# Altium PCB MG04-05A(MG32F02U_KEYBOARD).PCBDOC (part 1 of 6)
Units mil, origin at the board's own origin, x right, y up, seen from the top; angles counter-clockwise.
Board outline 17912.8 x 10422.68 mil, 2 copper layers (Top Layer, Bottom Layer); 623 components, 347 nets, 1816 pads, 821 vias.
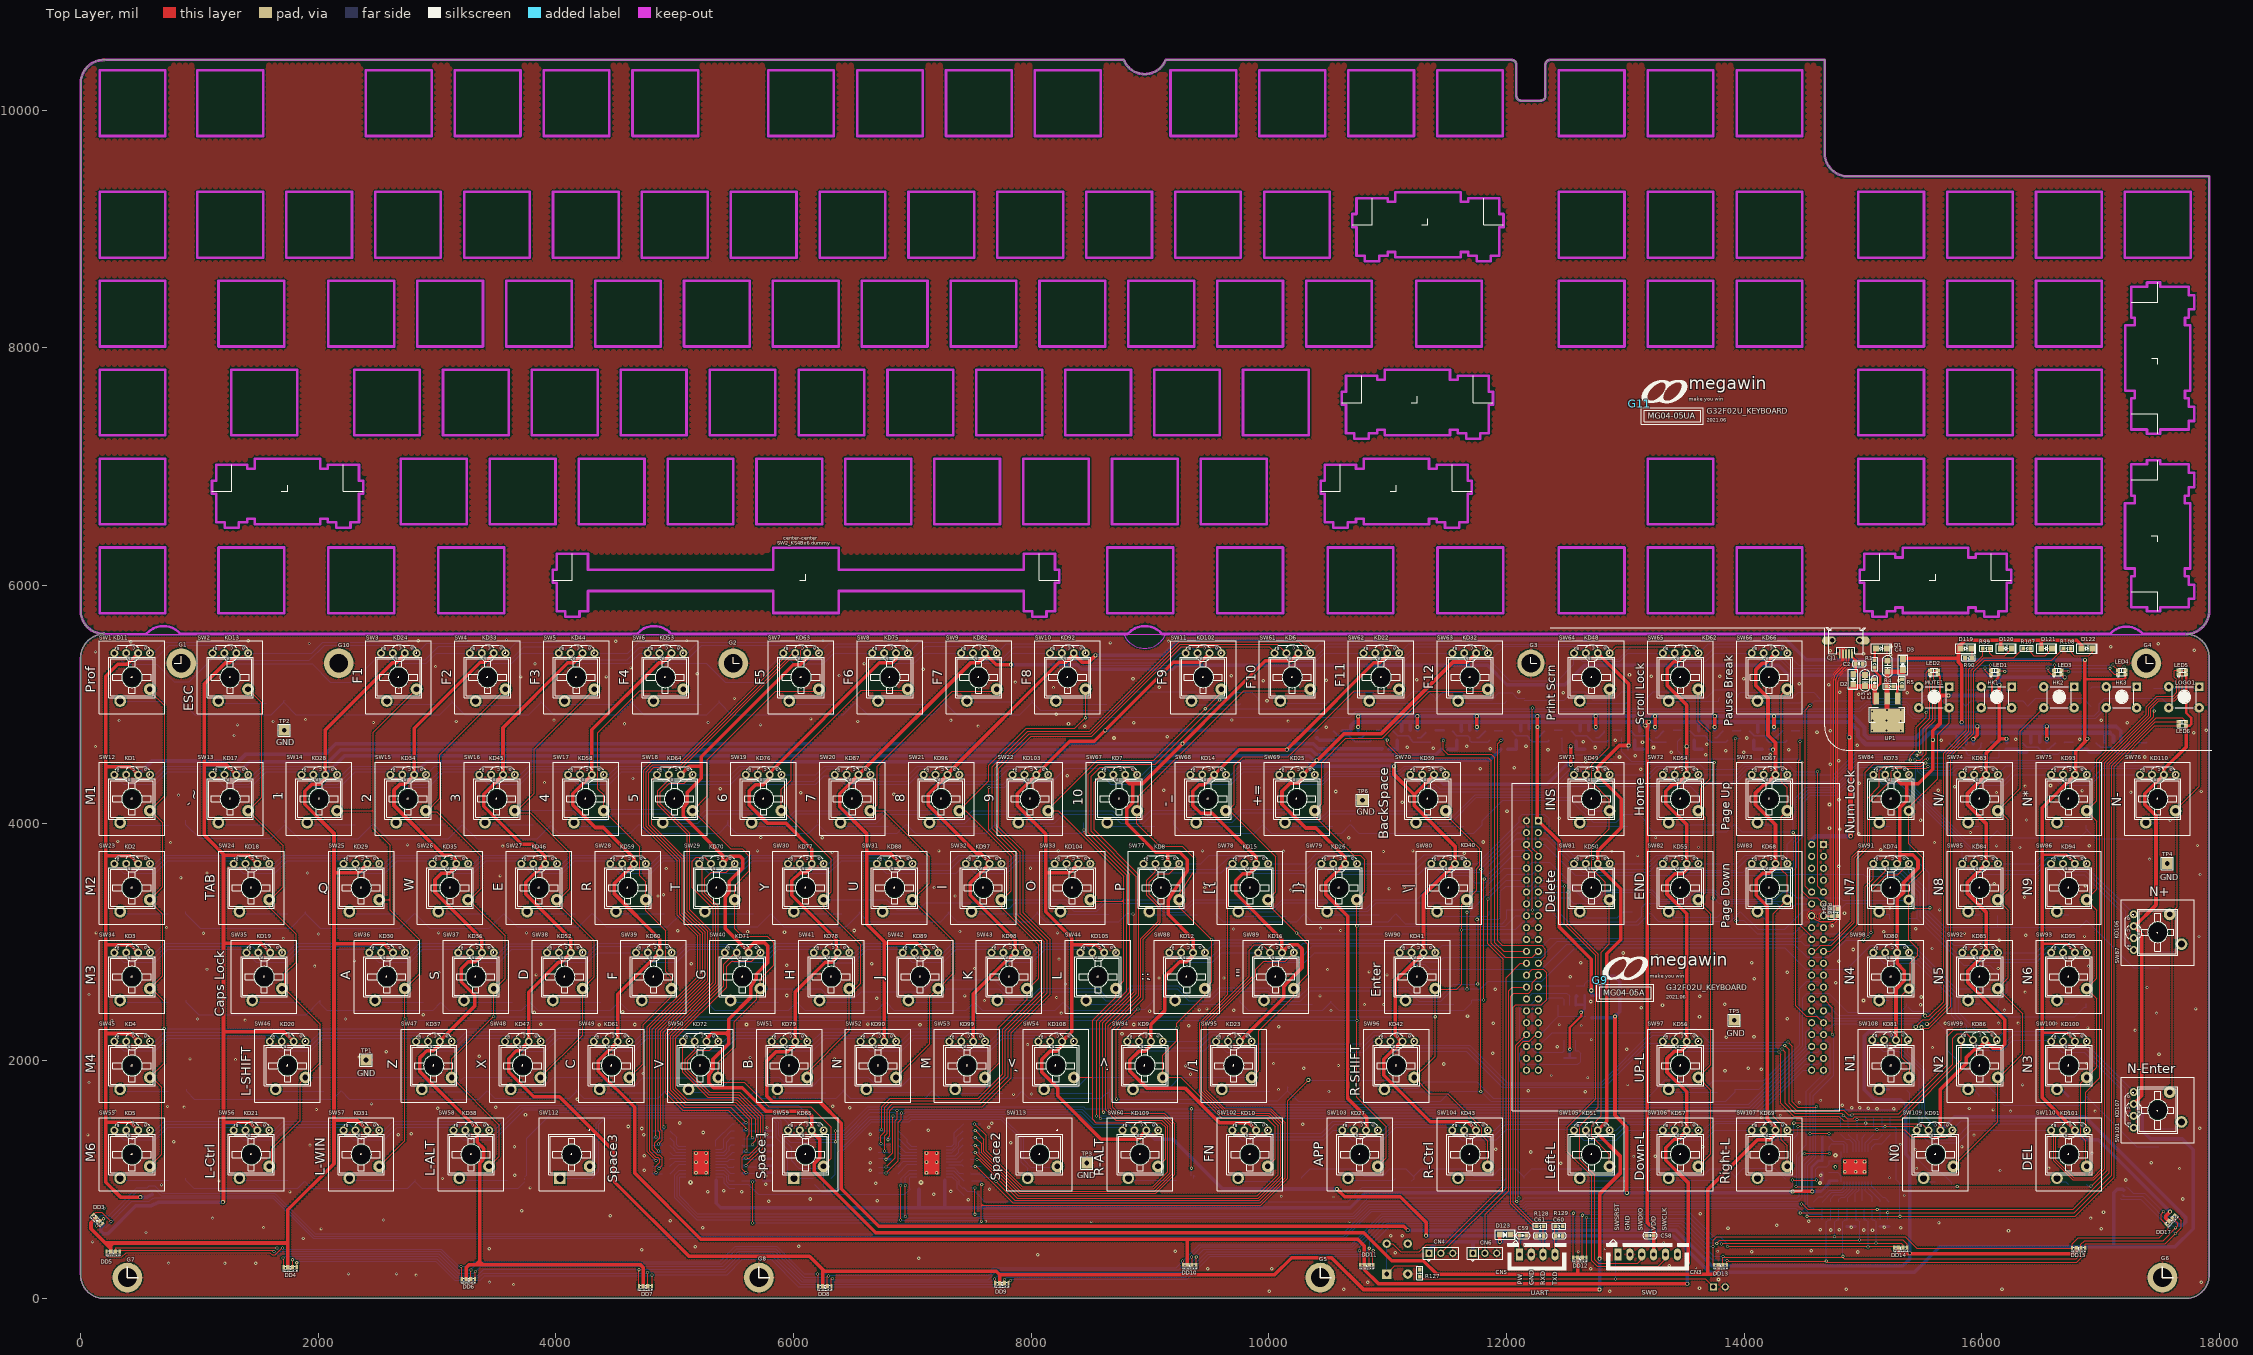
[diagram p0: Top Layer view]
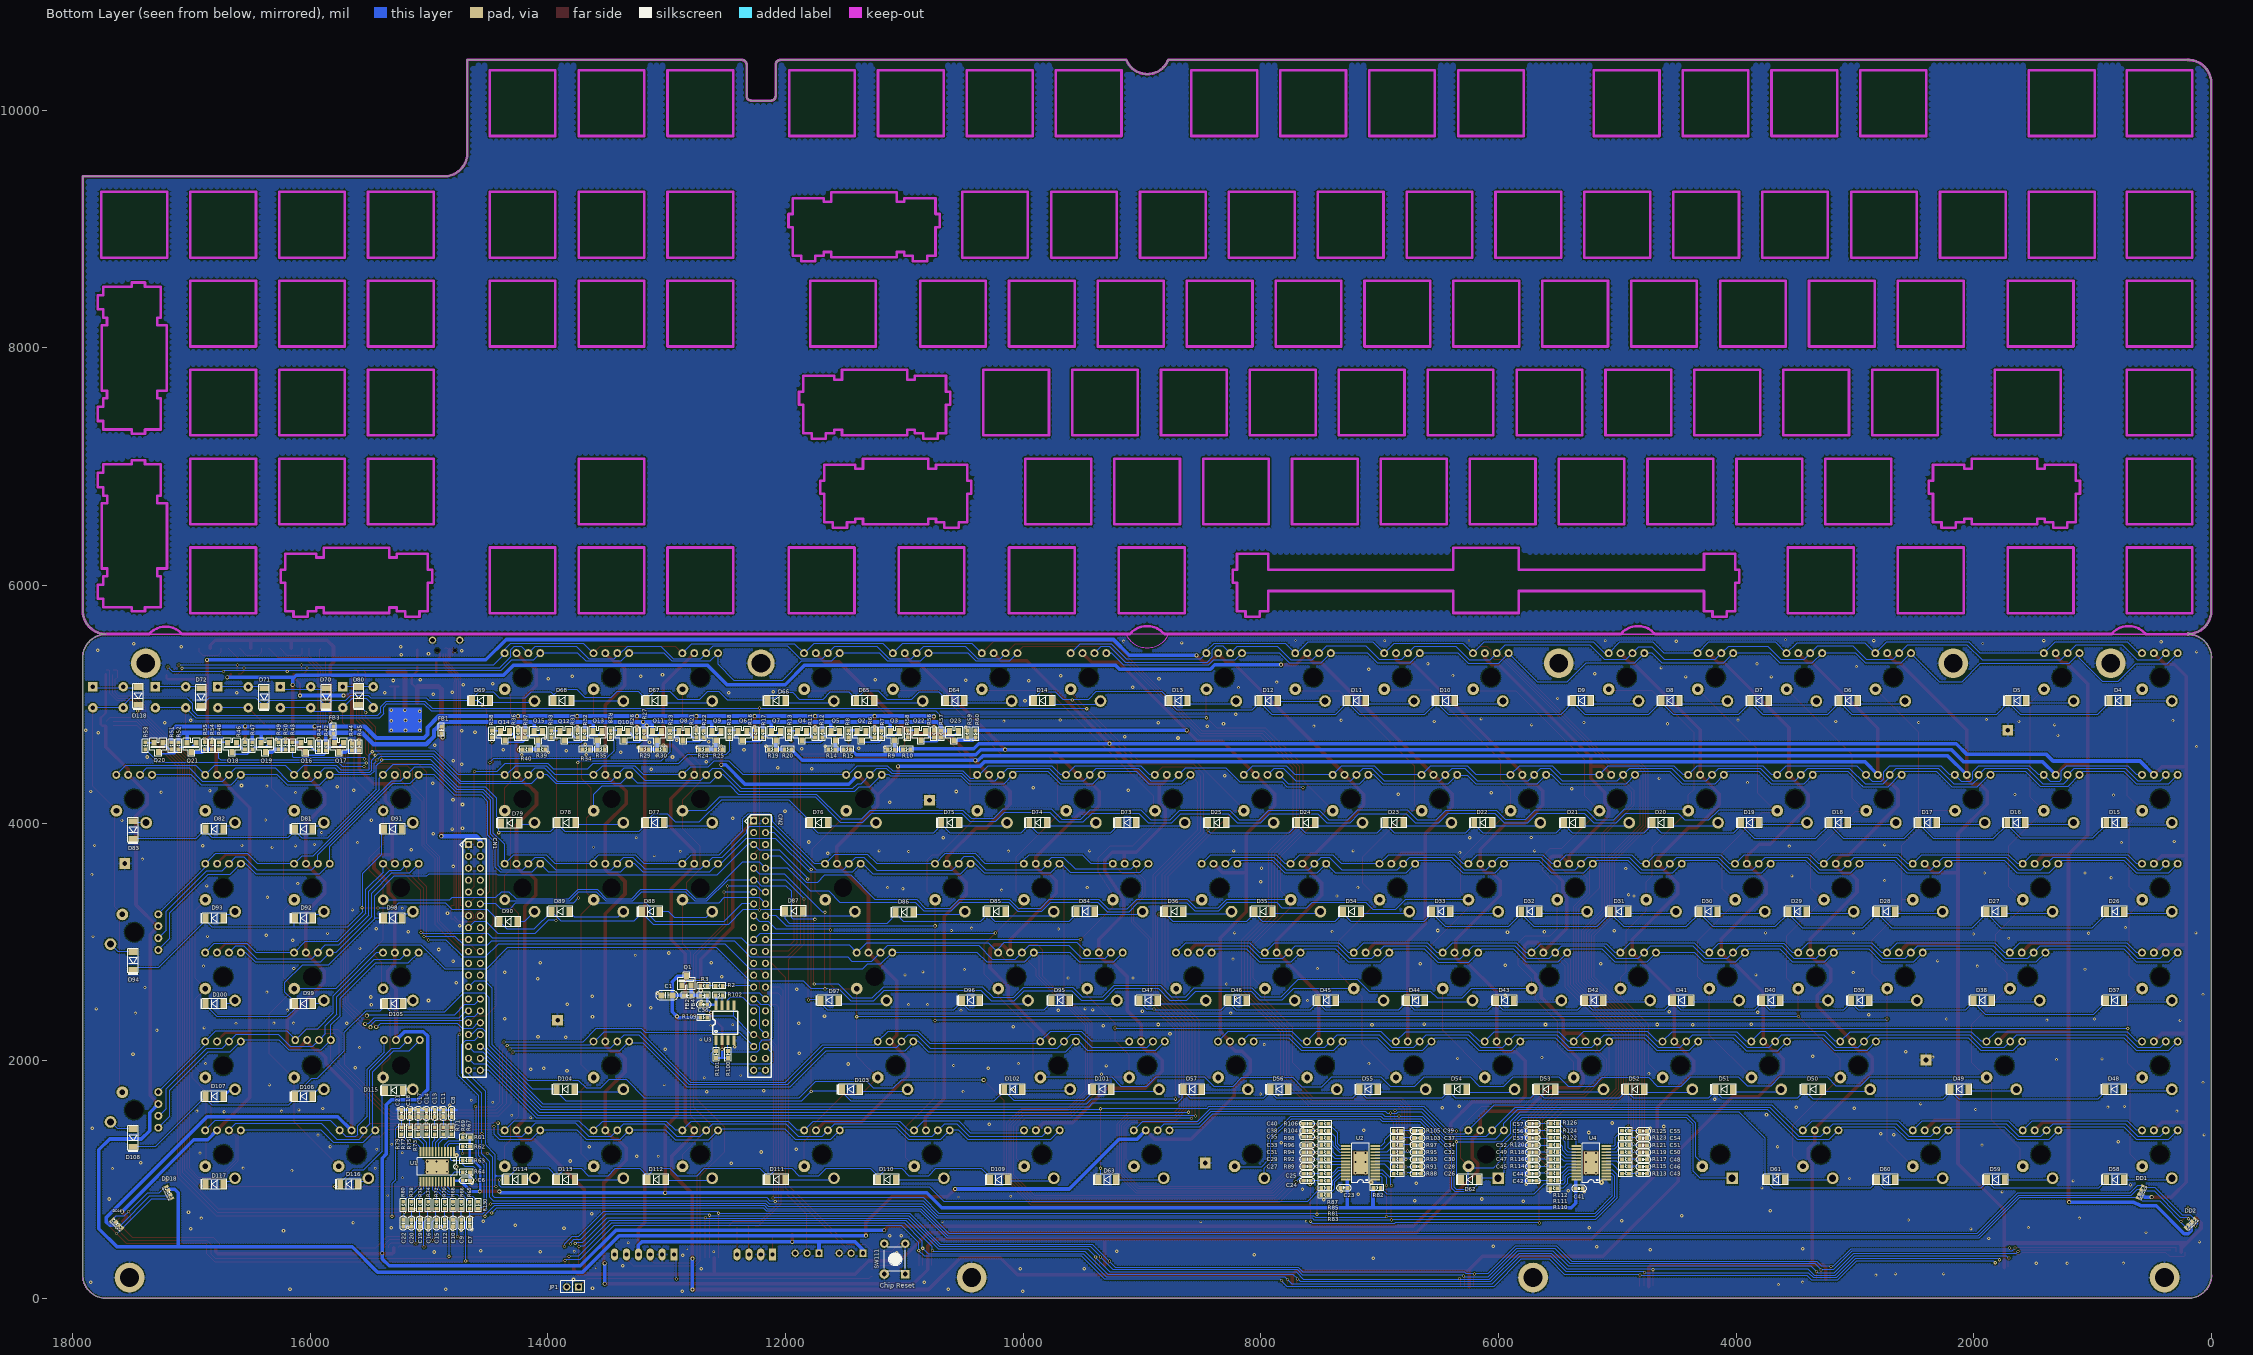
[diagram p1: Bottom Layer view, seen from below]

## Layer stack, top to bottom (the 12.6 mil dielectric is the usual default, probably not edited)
Top Layer: signal copper 1.4
Dielectric: dielectric 12.6, FR-4, Dk 4.8
Bottom Layer: signal copper 1.4

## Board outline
0,198.37 0,5393.85 cw(c196.85,5393.85) 196.85,5590.7 196.85,5590.95 cw(c196.85,5787.8) 0,5787.8 0,10225.83 cw(c196.85,10225.83) 196.85,10422.68 8778.93,10422.68 ccw(c8954.69,10492.11) 9130.28,10422.25 12042.69,10422.25 cw(c12042.7,10382.9) 12082.06,10382.89 12082.06,10119.37 ccw(c12121.43,10119.37) 12121.43,10080 12286.78,10080 ccw(c12286.78,10119.37) 12326.15,10119.37 12326.15,10382.89 cw(c12365.52,10382.88) 12365.52,10422.25 14676.35,10422.25 14676.35,9639.56 ccw(c14873.2,9639.56) 14873.2,9442.71 17912.8,9442.71 17912.8,5787.19 cw(c17715.95,5787.19) 17715.95,5590.34 17715.95,5590.55 cw(c17715.95,5393.7) 17912.8,5393.7 17912.8,198.37 cw(c17715.09,197.71) 17715.75,0 197.04,0 cw(c197.71,197.71)

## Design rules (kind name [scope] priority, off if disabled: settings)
Clearance 10 [All] p1 off: gap=10
Clearance 7_USB [All] p2 off: gap=7
Clearance 6_CLK [All] p3 off: gap=6
Clearance 5 [All] p4: gap=5
HoleSize [All] p1: absolutevalues=TRUE maxlimit=500 minlimit=1 maxpercent=80.000 minpercent=20.000
MinimumSolderMaskSliver [All] p1 off: minsoldermaskwidth=10
PolygonConnect via [isvia] p1: connectstyle=Direct reliefconductorwidth=10 reliefentries=4 polygonreliefangle="90 Angle"
PolygonConnect 15 [All] p2: connectstyle=Relief reliefconductorwidth=15 reliefentries=4 polygonreliefangle="90 Angle"
RoutingVias [All] p1: holewidth=16 width=25 viastyle="Through Hole" minholewidth=16 minwidth=25 maxholewidth=28 maxwidth=50
SilkToSilkClearance [All] p1 off: silktosilkclearance=10
SilkscreenOverComponentPads [All] p1 off: minsilkscreentomaskgap=10
SolderMaskExpansion [All] p1: expansion=4
Width [All] p1: maxlimit=100 minlimit=6 preferedwidth=10
24 further rules are at their usual default settings.

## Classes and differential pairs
net class LED_Y[0..10]: LED_Y0 LED_Y1 LED_Y2 LED_Y3 LED_Y4 LED_Y5 LED_Y6 LED_Y7 LED_Y8 LED_Y9 LED_Y10
net class LED_R[0..14]: LED_R0 LED_R1 LED_R2 LED_R3 LED_R4 LED_R5 LED_R6 LED_R7 LED_R8 LED_R9 LED_R10 LED_R11 LED_R12 LED_R13 LED_R14
net class LED_G[0..14]: LED_G0 LED_G1 LED_G2 LED_G3 LED_G4 LED_G5 LED_G6 LED_G7 LED_G8 LED_G9 LED_G10 LED_G11 LED_G12 LED_G13 LED_G14
net class LED_B[0..14]: LED_B0 LED_B1 LED_B2 LED_B3 LED_B4 LED_B5 LED_B6 LED_B7 LED_B8 LED_B9 LED_B10 LED_B11 LED_B12 LED_B13 LED_B14
net class KB_R[0..10]: KB_R0 KB_R1 KB_R2 KB_R3 KB_R4 KB_R5 KB_R6 KB_R7 KB_R8 KB_R9 KB_R10
net class KB_C[0..11]: KB_C0 KB_C1 KB_C2 KB_C3 KB_C4 KB_C5 KB_C6 KB_C7 KB_C8 KB_C9 KB_C10 KB_C11
component class "04_MCU IF": C6 C7 C8 C9 C10 C11 C12 C13 C14 C15 C16 C17 C18 C19 C20 C21 C22 C23 C24 C25 C26 C27 C28 C29 C30 C31 C32 C33 C34 C35 C36 C37 C38 C39 C40 C41 C42 C43 C44 C45 C46 C47 C48 C49 C50 C51 C52 C53 C54 C55 C56 C57 C58 C59 C60 C61 CN1 CN2 CN3 CN4 CN5 CN6 D119 D120 D121 D122 D123 FB4 JP1 R61 R62 R63 R64 R65 R66 R67 R68 R69 R70 R71 R72 R73 R74 R75 R76 R77 R78 R79 R80 R81 R82 R83 R84 R85 R86 R87 R88 R89 R90 R91 R92 R93 R94 R95 R96 R97 R98 R99 R100 R101 R102 R103 R104 R105 R106 R107 R108 R109 R110 R111 R112 R113 R114 R115 R116 R117 R118 R119 R120 R121 R122 R123 R124 R125 R126 R127 R128 R129 R130 SW111 U1 U2 U3 U4
component class "03_LED Matrix": DD1 DD2 DD3 DD4 DD5 DD6 DD7 DD8 DD9 DD10 DD11 DD12 DD13 DD14 DD15 DD16 DD17 DD18 KD1 KD2 KD3 KD4 KD5 KD6 KD7 KD8 KD9 KD10 KD11 KD12 KD13 KD14 KD15 KD16 KD17 KD18 KD19 KD20 KD21 KD22 KD23 KD24 KD25 KD26 KD27 KD28 KD29 KD30 KD31 KD32 KD33 KD34 KD35 KD36 KD37 KD38 KD39 KD40 KD41 KD42 KD43 KD44 KD45 KD46 KD47 KD48 KD49 KD50 KD51 KD52 KD53 KD54 KD55 KD56 KD57 KD58 KD59 KD60 KD61 KD62 KD63 KD64 KD65 KD66 KD67 KD68 KD69 KD70 KD71 KD72 KD73 KD74 KD75 KD76 KD77 KD78 KD79 KD80 KD81 KD82 KD83 KD84 KD85 KD86 KD87 KD88 KD89 KD90 KD91 KD92 KD93 KD94 KD95 KD96 KD97 KD98 KD99 KD100 KD101 KD102 KD103 KD104 KD105 KD106 KD107 KD108 KD109 KD110 LED1 LED2 LED3 LED4 LED5 LED6 Q2 Q3 Q4 Q5 Q6 Q7 Q8 Q9 Q10 Q11 Q12 Q13 Q14 Q15 Q16 Q17 Q18 Q19 Q20 Q21 Q22 Q23 R6 R7 R8 R9 R10 R11 R12 R13 R14 R15 R16 R17 R18 R19 R20 R21 R22 R23 R24 R25 R26 R27 R28 R29 R30 R31 R32 R33 R34 R35 R36 R37 R38 R39 R40 R41 R42 R43 R44 R45 R46 R47 R48 R49 R50 R51 R52 R53 R54 R55 R56 R57 R58 R59 R60
component class "02_Key Matrix": D4 D5 D6 D7 D8 D9 D10 D11 D12 D13 D14 D15 D16 D17 D18 D19 D20 D21 D22 D23 D24 D25 D26 D27 D28 D29 D30 D31 D32 D33 D34 D35 D36 D37 D38 D39 D40 D41 D42 D43 D44 D45 D46 D47 D48 D49 D50 D51 D52 D53 D54 D55 D56 D57 D58 D59 D60 D61 D62 D63 D64 D65 D66 D67 D68 D69 D70 D71 D72 D73 D74 D75 D76 D77 D78 D79 D80 D81 D82 D83 D84 D85 D86 D87 D88 D89 D90 D91 D92 D93 D94 D95 D96 D97 D98 D99 D100 D101 D102 D103 D104 D105 D106 D107 D108 D109 D110 D111 D112 D113 D114 D115 D116 D117 D118 HK1 HK2 HK3 Logo1 Mute1 SW1 SW2 SW3 SW4 SW5 SW6 SW7 SW8 SW9 SW10 SW11 SW12 SW13 SW14 SW15 SW16 SW17 SW18 SW19 SW20 SW21 SW22 SW23 SW24 SW25 SW26 SW27 SW28 SW29 SW30 SW31 SW32 SW33 SW34 SW35 SW36 SW37 SW38 SW39 SW40 SW41 SW42 SW43 SW44 SW45 SW46 SW47 SW48 SW49 SW50 SW51 SW52 SW53 SW54 SW55 SW56 SW57 SW58 SW59 SW60 SW61 SW62 SW63 SW64 SW65 SW66 SW67 SW68 SW69 SW70 SW71 SW72 SW73 SW74 SW75 SW76 SW77 SW78 SW79 SW80 SW81 SW82 SW83 SW84 SW85 SW86 SW87 SW88 SW89 SW90 SW91 SW92 SW93 SW94 SW95 SW96 SW97 SW98 SW99 SW100 SW101 SW102 SW103 SW104 SW105 SW106 SW107 SW108 SW109 SW110 SW112 SW113
component class "01_Power Supply": C1 C2 C3 C4 C5 CJ1 D1 D2 D3 FB1 FB2 FB3 G1 G2 G3 G4 G5 G6 G7 G8 G9 G10 G11 Q1 R1 R2 R3 R4 R5 TP1 TP2 TP3 TP4 TP5 TP6 UP1

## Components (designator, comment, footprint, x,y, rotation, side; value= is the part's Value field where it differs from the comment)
C1 "33uF/10V" C-0805 12997,2550 r0 bottom
C2 "1uF" C-0603 14967,5340 r0 top
C3 "10uF/10V" C-0805 15017,5200 r90 top
C4 "0.1uF" C-0603 15097,5180 r90 top
C5 "10uF/10V" C-0805 15207,5320 r90 top
C6 "0.1uF" C-0603 14684.64,992.74 r180 bottom
C7 "22pF" C-0603 14656,633.89 r270 bottom
C8 "22pF" C-0603 14808.15,1556.47 r90 bottom
C9 "22pF" C-0603 14726,633.89 r270 bottom
C10 "22pF" C-0603 14796,633.89 r270 bottom
C11 "22pF" C-0603 14880,1556.47 r90 bottom
C12 "22pF" C-0603 14866,633.89 r270 bottom
C13 "22pF" C-0603 14950,1556.47 r90 bottom
C14 "22pF" C-0603 15020,1556.47 r90 bottom
C15 "22pF" C-0603 14936,633.89 r270 bottom
C16 "22pF" C-0603 15006,633.89 r270 bottom
C17 "22pF" C-0603 15090,1556.47 r90 bottom (schematic designator C65)
C18 "22pF" C-0603 15160,1556.47 r90 bottom (schematic designator C66)
C19 "22pF" C-0603 15076,633.89 r270 bottom (schematic designator C46)
C20 "22pF" C-0603 15146,633.89 r270 bottom (schematic designator C47)
C21 "22pF" C-0603 15230,1556.47 r90 bottom (schematic designator C15)
C22 "22pF" C-0603 15216,633.89 r270 bottom (schematic designator C17)
C23 "0.1uF" C-0603 7300,929.89 r0 bottom (schematic designator C19)
C24 "22pF" C-0603 7610,989.89 r0 bottom (schematic designator C21)
C25 "22pF" C-0603 7610,1049.89 r0 bottom (schematic designator C23)
C26 "22pF" C-0603 6680,1049.89 r180 bottom (schematic designator C25)
C27 "22pF" C-0603 7610,1109.89 r0 bottom
C28 "22pF" C-0603 6680,1109.89 r180 bottom (schematic designator C61)
C29 "22pF" C-0603 7610,1169.89 r0 bottom (schematic designator C63)
C30 "22pF" C-0603 6680,1169.89 r180 bottom (schematic designator C62)
C31 "22pF" C-0603 7610,1229.89 r0 bottom (schematic designator C64)
C32 "22pF" C-0603 6680,1229.89 r180 bottom (schematic designator C42)
C33 "22pF" C-0603 7610,1289.89 r0 bottom (schematic designator C44)
C34 "22pF" C-0603 6680,1289.89 r180 bottom (schematic designator C43)
C35 "22pF" C-0603 7610,1359.89 r0 bottom (schematic designator C45)
C36 "1uF" C-0603 12687,2472.74 r0 bottom (schematic designator C57)
C37 "22pF" C-0603 6680,1349.89 r180 bottom (schematic designator C59)
C38 "22pF" C-0603 7610,1409.89 r0 bottom (schematic designator C58)
C39 "22pF" C-0603 6680,1409.89 r180 bottom (schematic designator C60)
C40 "22pF" C-0603 7610,1469.89 r0 bottom (schematic designator C38)
C41 "0.1uF" C-0603 5320,924.89 r180 bottom (schematic designator C40)
C42 "22pF" C-0603 5710,989.89 r0 bottom (schematic designator C39)
C43 "22pF" C-0603 4780,1049.89 r180 bottom (schematic designator C41)
C44 "22pF" C-0603 5710,1049.89 r0 bottom (schematic designator C55)
C45 "22pF" C-0603 5710,1109.89 r0 bottom (schematic designator C56)
C46 "22pF" C-0603 4779.42,1108.8 r180 bottom (schematic designator C36)
C47 "22pF" C-0603 5710,1169.89 r0 bottom (schematic designator C37)
C48 "22pF" C-0603 4779.42,1168.8 r180 bottom (schematic designator C53)
C49 "22pF" C-0603 5710,1229.89 r0 bottom (schematic designator C52)
C50 "22pF" C-0603 4779.42,1228.8 r180 bottom (schematic designator C54)
C51 "22pF" C-0603 4779.42,1288.8 r180 bottom (schematic designator C34)
C52 "22pF" C-0603 5710,1289.89 r0 bottom (schematic designator C33)
C53 "22pF" C-0603 5710,1349.89 r0 bottom (schematic designator C35)
C54 "22pF" C-0603 4779.42,1348.8 r180 bottom (schematic designator C50)
C55 "22pF" C-0603 4779.42,1408.8 r180 bottom (schematic designator C51)
C56 "22pF" C-0603 5710,1409.89 r0 bottom (schematic designator C31)
C57 "22pF" C-0603 5710,1469.89 r0 bottom (schematic designator C32)
C58 "0.1uF" C-0603 13207,530 r180 top (schematic designator C11)
C59 "0.1uF" C-0603 12137,530 r0 top (schematic designator C13)
C60 "47pF" C-0603 12442,526.47 r0 top (schematic designator C14)
C61 "47pF" C-0603 12282,526.47 r180 top (schematic designator C16)
CJ1 "CJ-USB-Micro" USB5A-MICRO-290X220P065 14855,5424.1 r270 top locked
CN1 "HEADER20X2-2.54-Female" HD20X2-P2.54 14667,3820 r270 bottom locked
CN2 "HEADER22X2-2.54-Female" HD22X2-P2.54 12267,4020 r270 bottom locked
CN3 "SIP6-2.54mm" HD6-P2.54-UL 13187,370 r0 top locked
CN4 "HEADER_3" SIP3-P2.54 11347,380 r0 top
CN5 "SIP4-2.54mm" HD4-P2.54-Z12.4X5.7X7-UL 12257,370 r0 top
CN6 "HEADER_3" SIP3-P2.54 11717,380 r0 top
D1 "LED0805-Green" LED-0805 15157,5470 r90 top
D2 "B5817" D-0805 14917,5210 r0 top
D3 "B5817" D-0805 15334.25,5333.13 r180 top
D4 "1N4148" DIODE_DO213AA 780,5029.8 r0 bottom (schematic designator D1)
D5 "1N4148" DIODE_DO213AA 1633.15,5029.8 r0 bottom (schematic designator D2)
D6 "1N4148" DIODE_DO213AA 3053.15,5029.8 r0 bottom (schematic designator D3)
D7 "1N4148" DIODE_DO213AA 3803.15,5029.8 r0 bottom (schematic designator D4)
D8 "1N4148" DIODE_DO213AA 4553.15,5029.8 r0 bottom (schematic designator D5)
D9 "1N4148" DIODE_DO213AA 5297.95,5029.8 r0 bottom (schematic designator D6)
D10 "1N4148" DIODE_DO213AA 6443.15,5029.8 r0 bottom (schematic designator D7)
D11 "1N4148" DIODE_DO213AA 7193.15,5029.8 r0 bottom (schematic designator D8)
D12 "1N4148" DIODE_DO213AA 7933.15,5029.8 r0 bottom (schematic designator D9)
D13 "1N4148" DIODE_DO213AA 8693.15,5029.8 r0 bottom (schematic designator D10)
D14 "1N4148" DIODE_DO213AA 9833.15,5029.8 r0 bottom (schematic designator D11)
D15 "1N4148" DIODE_DO213AA 810,4003.3 r0 bottom (schematic designator D12)
D16 "1N4148" DIODE_DO213AA 1643.15,4003.3 r0 bottom (schematic designator D13)
D17 "1N4148" DIODE_DO213AA 2388.19,4003.3 r0 bottom (schematic designator D14)
D18 "1N4148" DIODE_DO213AA 3137.95,4003.3 r0 bottom (schematic designator D15)
D19 "1N4148" DIODE_DO213AA 3883.15,4003.3 r0 bottom (schematic designator D16)
D20 "1N4148" DIODE_DO213AA 4627.95,4003.3 r0 bottom (schematic designator D17)
D21 "1N4148" DIODE_DO213AA 5373.15,4003.3 r0 bottom (schematic designator D18)
D22 "1N4148" DIODE_DO213AA 6127.95,4003.3 r0 bottom (schematic designator D19)
D23 "1N4148" DIODE_DO213AA 6873.15,4003.3 r0 bottom (schematic designator D20)
D24 "1N4148" DIODE_DO213AA 7617.95,4003.3 r0 bottom (schematic designator D21)
D25 "1N4148" DIODE_DO213AA 8367.95,4003.3 r0 bottom (schematic designator D22)
D26 "1N4148" DIODE_DO213AA 810,3254.89 r0 bottom (schematic designator D23)
D27 "1N4148" DIODE_DO213AA 1818.35,3254.89 r0 bottom (schematic designator D24)
D28 "1N4148" DIODE_DO213AA 2737.95,3254.89 r0 bottom (schematic designator D25)
D29 "1N4148" DIODE_DO213AA 3483.15,3254.89 r0 bottom (schematic designator D26)
D30 "1N4148" DIODE_DO213AA 4233.15,3254.89 r0 bottom (schematic designator D27)
D31 "1N4148" DIODE_DO213AA 4983.15,3254.89 r0 bottom (schematic designator D28)
D32 "1N4148" DIODE_DO213AA 5733.15,3254.89 r0 bottom (schematic designator D29)
D33 "1N4148" DIODE_DO213AA 6483.15,3254.89 r0 bottom (schematic designator D30)
D34 "1N4148" DIODE_DO213AA 7233.15,3254.89 r0 bottom (schematic designator D31)
D35 "1N4148" DIODE_DO213AA 7977.95,3254.89 r0 bottom (schematic designator D32)
D36 "1N4148" DIODE_DO213AA 8727.95,3254.89 r0 bottom (schematic designator D33)
D37 "1N4148" DIODE_DO213AA 812.08,2507.29 r0 bottom (schematic designator D34)
D38 "1N4148" DIODE_DO213AA 1925.23,2507.29 r0 bottom (schematic designator D35)
D39 "1N4148" DIODE_DO213AA 2955.23,2507.29 r0 bottom (schematic designator D36)
D40 "1N4148" DIODE_DO213AA 3705.23,2507.29 r0 bottom (schematic designator D37)
D41 "1N4148" DIODE_DO213AA 4455.23,2507.29 r0 bottom (schematic designator D38)
D42 "1N4148" DIODE_DO213AA 5195.23,2507.29 r0 bottom (schematic designator D39)
D43 "1N4148" DIODE_DO213AA 5945.23,2507.29 r0 bottom (schematic designator D40)
D44 "1N4148" DIODE_DO213AA 6695.23,2507.29 r0 bottom (schematic designator D41)
D45 "1N4148" DIODE_DO213AA 7445.23,2507.29 r0 bottom (schematic designator D42)
D46 "1N4148" DIODE_DO213AA 8195.23,2507.29 r0 bottom (schematic designator D43)
D47 "1N4148" DIODE_DO213AA 8945.23,2507.29 r0 bottom (schematic designator D44)
D48 "1N4148" DIODE_DO213AA 815.93,1759.19 r0 bottom (schematic designator D45)
D49 "1N4148" DIODE_DO213AA 2119.08,1759.19 r0 bottom (schematic designator D46)
D50 "1N4148" DIODE_DO213AA 3349.08,1759.19 r0 bottom (schematic designator D48)
D51 "1N4148" DIODE_DO213AA 4099.08,1759.19 r0 bottom (schematic designator D49)
D52 "1N4148" DIODE_DO213AA 4849.08,1759.19 r0 bottom (schematic designator D50)
D53 "1N4148" DIODE_DO213AA 5599.08,1759.19 r0 bottom (schematic designator D51)
D54 "1N4148" DIODE_DO213AA 6344.28,1759.19 r0 bottom (schematic designator D52)
D55 "1N4148" DIODE_DO213AA 7093.88,1759.19 r0 bottom (schematic designator D53)
D56 "1N4148" DIODE_DO213AA 7843.88,1759.19 r0 bottom (schematic designator D54)
D57 "1N4148" DIODE_DO213AA 8573.88,1759.19 r0 bottom (schematic designator D55)
D58 "1N4148" DIODE_DO213AA 810,999.47 r0 bottom (schematic designator D56)
D59 "1N4148" DIODE_DO213AA 1813.15,999.47 r0 bottom (schematic designator D57)
D60 "1N4148" DIODE_DO213AA 2737.95,999.47 r0 bottom (schematic designator D58)
D61 "1N4148" DIODE_DO213AA 3663.15,999.47 r0 bottom (schematic designator D59)
D62 "1N4148" DIODE_DO213AA 6239.43,999.47 r0 bottom
D63 "1N4148" DIODE_DO213AA 9291.18,999.47 r0 bottom (schematic designator D66)
D64 "1N4148" DIODE_DO213AA 10570.95,5029.8 r0 bottom (schematic designator D67)
D65 "1N4148" DIODE_DO213AA 11328.95,5029.8 r0 bottom (schematic designator D68)
D66 "1N4148" DIODE_DO213AA 12075.95,5029.8 r0 bottom (schematic designator D69)
D67 "1N4148" DIODE_DO213AA 13095.15,5029.8 r0 bottom (schematic designator D71)
D68 "1N4148" DIODE_DO213AA 13877.35,5029.8 r0 bottom (schematic designator D72)
D69 "1N4148" DIODE_DO213AA 14563.15,5029.8 r0 bottom (schematic designator D73)
D70 "1N4148" DIODE_DO213AA 15863.21,5060 r270 bottom (schematic designator D74)
D71 "1N4148" DIODE_DO213AA 16387,5060 r270 bottom (schematic designator D75)
D72 "1N4148" DIODE_DO213AA 16917,5060 r270 bottom (schematic designator D76)
D73 "1N4148" DIODE_DO213AA 9123.15,4003.3 r0 bottom (schematic designator D78)
D74 "1N4148" DIODE_DO213AA 9873.15,4003.3 r0 bottom (schematic designator D79)
D75 "1N4148" DIODE_DO213AA 10613.15,4003.3 r0 bottom (schematic designator D80)
D76 "1N4148" DIODE_DO213AA 11718.35,4003.3 r0 bottom (schematic designator D81)
D77 "1N4148" DIODE_DO213AA 13097.95,4003.3 r0 bottom (schematic designator D82)
D78 "1N4148" DIODE_DO213AA 13843.15,4003.3 r0 bottom (schematic designator D83)
D79 "1N4148" DIODE_DO213AA 14317,4000 r0 bottom (schematic designator D84)
D80 "1N4148" DIODE_DO213AA 15589.6,5070.7 r270 bottom (schematic designator D85)
D81 "1N4148" DIODE_DO213AA 16053.15,3950 r0 bottom (schematic designator D86)
D82 "1N4148" DIODE_DO213AA 16803.15,3950 r0 bottom (schematic designator D87)
D83 "1N4148" DIODE_DO213AA 17489.6,3941.25 r270 bottom (schematic designator D88)
D84 "1N4148" DIODE_DO213AA 9473.15,3254.89 r0 bottom (schematic designator D89)
D85 "1N4148" DIODE_DO213AA 10223.15,3254.89 r0 bottom (schematic designator D90)
D86 "1N4148" DIODE_DO213AA 10997,3250 r0 bottom (schematic designator D91)
D87 "1N4148" DIODE_DO213AA 11927,3260 r0 bottom (schematic designator D92)
D88 "1N4148" DIODE_DO213AA 13133.15,3254.89 r0 bottom (schematic designator D93)
D89 "1N4148" DIODE_DO213AA 13893.15,3254.89 r0 bottom (schematic designator D94)
D90 "1N4148" DIODE_DO213AA 14330,3169.89 r0 bottom (schematic designator D95)
D91 "1N4148" DIODE_DO213AA 15303.15,3950 r0 bottom (schematic designator D96)
D92 "1N4148" DIODE_DO213AA 16053.15,3200 r0 bottom (schematic designator D97)
D93 "1N4148" DIODE_DO213AA 16803.15,3200 r0 bottom (schematic designator D98)
D94 "1N4148" DIODE_DO213AA 17489.6,2841.25 r270 bottom (schematic designator D99)
D95 "1N4148" DIODE_DO213AA 9685.23,2507.29 r0 bottom (schematic designator D100)
D96 "1N4148" DIODE_DO213AA 10440.04,2507.29 r0 bottom (schematic designator D101)
D97 "1N4148" DIODE_DO213AA 11630.04,2507.29 r0 bottom (schematic designator D103)
D98 "1N4148" DIODE_DO213AA 15303.15,3200 r0 bottom (schematic designator D104)
D99 "1N4148" DIODE_DO213AA 16053.15,2480 r0 bottom (schematic designator D105)
D100 "1N4148" DIODE_DO213AA 16803.15,2480 r0 bottom (schematic designator D106)
D101 "1N4148" DIODE_DO213AA 9333.88,1759.19 r0 bottom (schematic designator D108)
D102 "1N4148" DIODE_DO213AA 10083.78,1759.19 r0 bottom (schematic designator D109)
D103 "1N4148" DIODE_DO213AA 11450.04,1758.74 r0 bottom (schematic designator D111)
D104 "1N4148" DIODE_DO213AA 13849.08,1759.19 r0 bottom (schematic designator D112)
D105 "1N4148" DIODE_DO213AA 15293.15,2480 r0 bottom (schematic designator D113)
D106 "1N4148" DIODE_DO213AA 16053.15,1700 r0 bottom (schematic designator D114)
D107 "1N4148" DIODE_DO213AA 16803.15,1700 r0 bottom (schematic designator D115)
D108 "1N4148" DIODE_DO213AA 17489.6,1351.25 r270 bottom (schematic designator D116)
D109 "1N4148" DIODE_DO213AA 10203.15,999.47 r0 bottom (schematic designator D117)
D110 "1N4148" DIODE_DO213AA 11143.15,999.47 r0 bottom (schematic designator D119)
D111 "1N4148" DIODE_DO213AA 12073.15,999.47 r0 bottom (schematic designator D120)
D112 "1N4148" DIODE_DO213AA 13083.15,999.47 r0 bottom (schematic designator D121)
D113 "1N4148" DIODE_DO213AA 13847.95,999.47 r0 bottom (schematic designator D122)
D114 "1N4148" DIODE_DO213AA 14270,999.47 r0 bottom (schematic designator D123)
D115 "1N4148" DIODE_DO213AA 15293.15,1750 r0 bottom (schematic designator D124)
D116 "1N4148" DIODE_DO213AA 15670.99,960 r0 bottom (schematic designator D125)
D117 "1N4148" DIODE_DO213AA 16803.15,960 r0 bottom (schematic designator D126)
D118 "1N4148" DIODE_DO213AA 17446.85,5070.7 r270 bottom (schematic designator D127)
D119 "LED0805-White" LED-0805 15867,5470 r90 top (schematic designator Num)
D120 "LED0805-White" LED-0805 16207,5470 r90 top (schematic designator Caps)
D121 "LED0805-White" LED-0805 16547,5470 r90 top (schematic designator Scroll)
D122 "LED0805-White" LED-0805 16887,5470 r90 top (schematic designator Game)
D123 "B5817" D-0805 11988,536.47 r90 top
DD1 "LTST-S33FBEGW" LED4P_SMD_3X1_CRGB 586.15,890 r295 bottom (schematic designator LD138)
DD2 "LTST-S33FBEGW" LED4P_SMD_3X1_CRGB 167.88,624.68 r315 bottom (schematic designator LD137)
DD3 "LTST-S33FBEGW" LED4P_SMD_3X1_CRGB 135.71,656.85 r135 top (schematic designator LD136)
DD4 "LTST-S33FBEGW" LED4P_SMD_3X1_CRGB 1763.15,250 r180 top (schematic designator LD139)
DD5 "LTST-S33FBEGW" LED4P_SMD_3X1_CRGB 273.15,380 r180 top (schematic designator LD141)
DD6 "LTST-S33FBEGW" LED4P_SMD_3X1_CRGB 3263.15,150 r180 top (schematic designator LD142)
DD7 "LTST-S33FBEGW" LED4P_SMD_3X1_CRGB 4753.15,90.11 r180 top (schematic designator LD140)
DD8 "LTST-S33FBEGW" LED4P_SMD_3X1_CRGB 6263.15,89.69 r180 top (schematic designator LD143)
DD9 "LTST-S33FBEGW" LED4P_SMD_3X1_CRGB 7753.15,115.18 r180 top (schematic designator LD135)
DD10 "LTST-S33FBEGW" LED4P_SMD_3X1_CRGB 9333.15,270 r180 top (schematic designator LD144)
DD11 "LTST-S33FBEGW" LED4P_SMD_3X1_CRGB 10823.15,270 r180 top (schematic designator LD134)
DD12 "LTST-S33FBEGW" LED4P_SMD_3X1_CRGB 12617.15,330 r180 top (schematic designator LD145)
DD13 "LTST-S33FBEGW" LED4P_SMD_3X1_CRGB 13800.15,270 r180 top (schematic designator LD133)
DD14 "LTST-S33FBEGW" LED4P_SMD_3X1_CRGB 15316.48,415 r180 top (schematic designator LD146)
DD15 "LTST-S33FBEGW" LED4P_SMD_3X1_CRGB 16813.48,411 r180 top (schematic designator LD132)
DD16 "LTST-S33FBEGW" LED4P_SMD_3X1_CRGB 17629.15,620 r45 bottom (schematic designator LD131)
DD17 "LTST-S33FBEGW" LED4P_SMD_3X1_CRGB 17597.3,654.56 r225 top (schematic designator LD130)
DD18 "LTST-S33FBEGW" LED4P_SMD_3X1_CRGB 17196.15,887 r65 bottom (schematic designator LD129)
FB1 "FB_0805" L-0603 14894.6,4784.03 r90 bottom
FB2 "FB_0603" L-0603 12822,2550 r180 bottom
FB3 "FB_0805" L-0603 15804.6,4784.03 r270 bottom
FB4 "FB_0603" L-0603 12687,2550 r0 bottom
G1 "4mm_6.35via" SCREW1-H4-R6.35#1 846.53,5345.98 r0 top
G2 "4mm_6.35via" SCREW1-H4-R6.35#1 5492.2,5345.98 r0 top
G3 "4mm_6.35via" SCREW1-H4-R6.35#2 12204.8,5345.98 r0 top
G4 "4mm_6.35via" SCREW1-H4-R6.35#1 17381.96,5345.98 r0 top
G5 "4mm_6.35via" SCREW1-H4-R6.35#1 10432.67,175.65 r0 top
G6 "4mm_6.35via" SCREW1-H4-R6.35#1 17519.28,175.65 r0 top
G7 "4mm_6.35via" SCREW1-H4-R6.35#1 393.3,175.65 r0 top
G8 "4mm_6.35via" SCREW1-H4-R6.35#1 5708.26,175.65 r0 top
G9 "Logo_Megawin_3_4" MEGAWIN_4.9 12789.61,2677 r0 top
G10 "4mm_6.35via" SCREW1-H4-R6.35#1 2172,5345.98 r0 top
G11 "Logo_Megawin_3_4" MEGAWIN_4.9 13119.61,7530.4 r0 top
HK1 "SW-PB-4P" SW-TACT-P4.5X6.5-Z6.2X6.2X5#1 16250,5147 r180 top locked
HK2 "SW-PB-4P" SW-TACT-P4.5X6.5-Z6.2X6.2X5#1 16776,5147 r180 top locked
HK3 "SW-PB-4P" SW-TACT-P4.5X6.5-Z6.2X6.2X5#1 17302,5147 r180 top locked
JP1 "JUMPER" SIP2-P2.54 13739.76,96.91 r0 bottom
KD1 "LTL760RGBEBJ" LED_3.5_CRGB 433.27,4406.2 r180 top locked (schematic designator LD12)
KD2 "LTL760RGBEBJ" LED_3.5_CRGB 433.27,3657.8 r180 top locked (schematic designator LD23)
KD3 "LTL760RGBEBJ" LED_3.5_CRGB 433.27,2910.2 r180 top locked (schematic designator LD34)
KD4 "LTL760RGBEBJ" LED_3.5_CRGB 433.27,2162.1 r180 top locked (schematic designator LD45)
KD5 "LTL760RGBEBJ" LED_3.5_CRGB 433.27,1414.1 r180 top locked (schematic designator LD56)
KD6 "LTL760RGBEBJ" LED_3.5_CRGB 10197.07,5429.8 r180 top locked (schematic designator LD67)
KD7 "LTL760RGBEBJ" LED_3.5_CRGB 8740.38,4406.2 r180 top locked (schematic designator LD78)
KD8 "LTL760RGBEBJ" LED_3.5_CRGB 9094.75,3657.8 r180 top locked (schematic designator LD89)
KD9 "LTL760RGBEBJ" LED_3.5_CRGB 8956.93,2162.1 r180 top locked (schematic designator LD108)
KD10 "LTL760RGBEBJ" LED_3.5_CRGB 9841.76,1414.1 r180 top locked (schematic designator LD117)
KD11 "LTL760RGBEBJ" LED_3.5_CRGB 433.27,5429.8 r180 top locked (schematic designator LD1)
KD12 "LTL760RGBEBJ" LED_3.5_CRGB 9311.29,2910.2 r180 top locked (schematic designator LD100)
KD13 "LTL760RGBEBJ" LED_3.5_CRGB 1259.57,5429.8 r180 top locked (schematic designator LD2)
KD14 "LTL760RGBEBJ" LED_3.5_CRGB 9488.45,4406.2 r180 top locked (schematic designator LD79)
KD15 "LTL760RGBEBJ" LED_3.5_CRGB 9842.78,3657.8 r180 top locked (schematic designator LD90)
KD16 "LTL760RGBEBJ" LED_3.5_CRGB 10059.32,2910.2 r180 top locked (schematic designator LD101)
KD17 "LTL760RGBEBJ" LED_3.5_CRGB 1260.16,4406.2 r180 top locked (schematic designator LD13)
KD18 "LTL760RGBEBJ" LED_3.5_CRGB 1437.21,3657.8 r180 top locked (schematic designator LD24)
KD19 "LTL760RGBEBJ" LED_3.5_CRGB 1545.48,2910.2 r180 top locked (schematic designator LD35)
KD20 "LTL760RGBEBJ" LED_3.5_CRGB 1742.33,2162.1 r180 top locked (schematic designator LD46)
KD21 "LTL760RGBEBJ" LED_3.5_CRGB 1437.22,1414.1 r180 top locked (schematic designator LD57)
KD22 "LTL760RGBEBJ" LED_3.5_CRGB 10945.26,5429.8 r180 top locked (schematic designator LD68)
KD23 "LTL760RGBEBJ" LED_3.5_CRGB 9704.96,2162.1 r180 top locked (schematic designator LD109)
KD24 "LTL760RGBEBJ" LED_3.5_CRGB 2677.56,5429.8 r180 top locked (schematic designator LD3)
KD25 "LTL760RGBEBJ" LED_3.5_CRGB 10236.44,4406.2 r180 top locked (schematic designator LD80)
KD26 "LTL760RGBEBJ" LED_3.5_CRGB 10590.81,3657.8 r180 top locked (schematic designator LD91)
KD27 "LTL760RGBEBJ" LED_3.5_CRGB 10766.96,1414.1 r180 top locked (schematic designator LD119)
KD28 "LTL760RGBEBJ" LED_3.5_CRGB 2008.04,4406.2 r180 top locked (schematic designator LD14)
KD29 "LTL760RGBEBJ" LED_3.5_CRGB 2362.6,3657.8 r180 top locked (schematic designator LD25)
KD30 "LTL760RGBEBJ" LED_3.5_CRGB 2578.94,2910.2 r180 top locked (schematic designator LD36)
KD31 "LTL760RGBEBJ" LED_3.5_CRGB 2362.42,1414.1 r180 top locked (schematic designator LD58)
KD32 "LTL760RGBEBJ" LED_3.5_CRGB 11693.18,5429.8 r180 top locked (schematic designator LD69)
KD33 "LTL760RGBEBJ" LED_3.5_CRGB 3425.56,5429.8 r180 top locked (schematic designator LD4)
KD34 "LTL760RGBEBJ" LED_3.5_CRGB 2756.15,4406.2 r180 top locked (schematic designator LD15)
KD35 "LTL760RGBEBJ" LED_3.5_CRGB 3110.48,3657.8 r180 top locked (schematic designator LD26)
KD36 "LTL760RGBEBJ" LED_3.5_CRGB 3327.01,2910.2 r180 top locked (schematic designator LD37)
KD37 "LTL760RGBEBJ" LED_3.5_CRGB 2972.65,2162.1 r180 top locked (schematic designator LD48)
KD38 "LTL760RGBEBJ" LED_3.5_CRGB 3287.62,1414.1 r180 top locked (schematic designator LD59)
KD39 "LTL760RGBEBJ" LED_3.5_CRGB 11338.88,4406.2 r180 top locked (schematic designator LD81)
KD40 "LTL760RGBEBJ" LED_3.5_CRGB 11515.97,3657.8 r180 top locked (schematic designator LD92)
KD41 "LTL760RGBEBJ" LED_3.5_CRGB 11250.26,2910.2 r180 top locked (schematic designator LD103)
KD42 "LTL760RGBEBJ" LED_3.5_CRGB 11073.07,2162.1 r180 top locked (schematic designator LD111)
KD43 "LTL760RGBEBJ" LED_3.5_CRGB 11692.16,1414.1 r180 top locked (schematic designator LD120)
KD44 "LTL760RGBEBJ" LED_3.5_CRGB 4173.56,5429.8 r180 top locked (schematic designator LD5)
KD45 "LTL760RGBEBJ" LED_3.5_CRGB 3504.14,4406.2 r180 top locked (schematic designator LD16)
KD46 "LTL760RGBEBJ" LED_3.5_CRGB 3858.51,3657.8 r180 top locked (schematic designator LD27)
KD47 "LTL760RGBEBJ" LED_3.5_CRGB 3720.71,2162.1 r180 top locked (schematic designator LD49)
KD48 "LTL760RGBEBJ" LED_3.5_CRGB 12716.92,5429.8 r180 top locked (schematic designator LD71)
KD49 "LTL760RGBEBJ" LED_3.5_CRGB 12716.77,4406.2 r180 top locked (schematic designator LD82)
KD50 "LTL760RGBEBJ" LED_3.5_CRGB 12716.77,3657.8 r180 top locked (schematic designator LD93)
KD51 "LTL760RGBEBJ" LED_3.5_CRGB 12716.78,1414.1 r180 top locked (schematic designator LD121)
KD52 "LTL760RGBEBJ" LED_3.5_CRGB 4075.04,2910.2 r180 top locked (schematic designator LD38)
KD53 "LTL760RGBEBJ" LED_3.5_CRGB 4921.57,5429.8 r180 top locked (schematic designator LD6)
KD54 "LTL760RGBEBJ" LED_3.5_CRGB 13464.84,4406.2 r180 top locked (schematic designator LD83)
KD55 "LTL760RGBEBJ" LED_3.5_CRGB 13464.84,3657.8 r180 top locked (schematic designator LD94)
KD56 "LTL760RGBEBJ" LED_3.5_CRGB 13464.81,2162.1 r180 top locked (schematic designator LD112)
KD57 "LTL760RGBEBJ" LED_3.5_CRGB 13464.81,1414.1 r180 top locked (schematic designator LD122)
KD58 "LTL760RGBEBJ" LED_3.5_CRGB 4252.18,4406.2 r180 top locked (schematic designator LD17)
KD59 "LTL760RGBEBJ" LED_3.5_CRGB 4606.51,3657.8 r180 top locked (schematic designator LD28)
KD60 "LTL760RGBEBJ" LED_3.5_CRGB 4823.09,2910.2 r180 top locked (schematic designator LD39)
KD61 "LTL760RGBEBJ" LED_3.5_CRGB 4468.73,2162.1 r180 top locked (schematic designator LD50)
KD62 "LTL760RGBEBJ" LED_3.5_CRGB 13464.8,5429.8 r180 top locked (schematic designator LD72)
KD63 "LTL760RGBEBJ" LED_3.5_CRGB 6063.57,5429.8 r180 top locked (schematic designator LD7)
KD64 "LTL760RGBEBJ" LED_3.5_CRGB 5000.17,4406.2 r180 top locked (schematic designator LD18)
KD65 "LTL760RGBEBJ" LED_3.5_CRGB 6102.59,1414.1 r180 top locked (schematic designator LD62)
KD66 "LTL760RGBEBJ" LED_3.5_CRGB 14212.99,5429.8 r180 top locked (schematic designator LD73)
KD67 "LTL760RGBEBJ" LED_3.5_CRGB 14212.87,4406.2 r180 top locked (schematic designator LD84)
KD68 "LTL760RGBEBJ" LED_3.5_CRGB 14212.87,3657.8 r180 top locked (schematic designator LD95)
KD69 "LTL760RGBEBJ" LED_3.5_CRGB 14212.85,1414.1 r180 top locked (schematic designator LD123)
KD70 "LTL760RGBEBJ" LED_3.5_CRGB 5354.58,3657.8 r180 top locked (schematic designator LD29)
KD71 "LTL760RGBEBJ" LED_3.5_CRGB 5571.12,2910.2 r180 top locked (schematic designator LD40)
KD72 "LTL760RGBEBJ" LED_3.5_CRGB 5216.76,2162.1 r180 top locked (schematic designator LD51)
KD73 "LTL760RGBEBJ" LED_3.5_CRGB 15236.45,4406.2 r180 top locked (schematic designator LD96)
KD74 "LTL760RGBEBJ" LED_3.5_CRGB 15235.67,3657.8 r180 top locked (schematic designator LD104)
KD75 "LTL760RGBEBJ" LED_3.5_CRGB 6811.23,5429.8 r180 top locked (schematic designator LD8)
KD76 "LTL760RGBEBJ" LED_3.5_CRGB 5748.2,4406.2 r180 top locked (schematic designator LD19)
KD77 "LTL760RGBEBJ" LED_3.5_CRGB 6102.57,3657.8 r180 top locked (schematic designator LD30)
KD78 "LTL760RGBEBJ" LED_3.5_CRGB 6319.15,2910.2 r180 top locked (schematic designator LD41)
KD79 "LTL760RGBEBJ" LED_3.5_CRGB 5964.79,2162.1 r180 top locked (schematic designator LD52)
KD80 "LTL760RGBEBJ" LED_3.5_CRGB 15236.03,2910.2 r180 top locked (schematic designator LD113)
KD81 "LTL760RGBEBJ" LED_3.5_CRGB 15226.65,2174.11 r180 top locked (schematic designator LD124)
KD82 "LTL760RGBEBJ" LED_3.5_CRGB 7559.31,5429.8 r180 top locked (schematic designator LD9)
KD83 "LTL760RGBEBJ" LED_3.5_CRGB 15984.7,4406.2 r180 top locked (schematic designator LD86)
KD84 "LTL760RGBEBJ" LED_3.5_CRGB 15984.52,3657.8 r180 top locked (schematic designator LD97)
KD85 "LTL760RGBEBJ" LED_3.5_CRGB 15984.7,2910.2 r180 top locked (schematic designator LD105)
KD86 "LTL760RGBEBJ" LED_3.5_CRGB 15974.68,2174.11 r180 top locked (schematic designator LD114)
KD87 "LTL760RGBEBJ" LED_3.5_CRGB 6496.24,4406.2 r180 top locked (schematic designator LD20)
KD88 "LTL760RGBEBJ" LED_3.5_CRGB 6850.64,3657.8 r180 top locked (schematic designator LD31)
KD89 "LTL760RGBEBJ" LED_3.5_CRGB 7067.18,2910.2 r180 top locked (schematic designator LD42)
KD90 "LTL760RGBEBJ" LED_3.5_CRGB 6712.82,2162.1 r180 top locked (schematic designator LD53)
KD91 "LTL760RGBEBJ" LED_3.5_CRGB 15600.67,1414.1 r180 top locked (schematic designator LD125)
KD92 "LTL760RGBEBJ" LED_3.5_CRGB 8307.35,5429.8 r180 top locked (schematic designator LD10)
KD93 "LTL760RGBEBJ" LED_3.5_CRGB 16732.53,4406.2 r180 top locked (schematic designator LD87)
KD94 "LTL760RGBEBJ" LED_3.5_CRGB 16731.75,3657.8 r180 top locked (schematic designator LD98)
KD95 "LTL760RGBEBJ" LED_3.5_CRGB 16732.75,2910.2 r180 top locked (schematic designator LD106)
KD96 "LTL760RGBEBJ" LED_3.5_CRGB 7244.31,4406.2 r180 top locked (schematic designator LD21)
KD97 "LTL760RGBEBJ" LED_3.5_CRGB 7598.68,3657.8 r180 top locked (schematic designator LD32)
KD98 "LTL760RGBEBJ" LED_3.5_CRGB 7815.21,2910.2 r180 top locked (schematic designator LD43)
KD99 "LTL760RGBEBJ" LED_3.5_CRGB 7460.85,2162.1 r180 top locked (schematic designator LD54)
KD100 "LTL760RGBEBJ" LED_3.5_CRGB 16732.54,2162.1 r180 top locked (schematic designator LD115)
KD101 "LTL760RGBEBJ" LED_3.5_CRGB 16732.72,1414.1 r180 top locked (schematic designator LD126)
KD102 "LTL760RGBEBJ" LED_3.5_CRGB 9449.16,5429.8 r180 top locked (schematic designator LD11)
KD103 "LTL760RGBEBJ" LED_3.5_CRGB 7992.3,4406.2 r180 top locked (schematic designator LD22)
KD104 "LTL760RGBEBJ" LED_3.5_CRGB 8346.72,3657.8 r180 top locked (schematic designator LD33)
KD105 "LTL760RGBEBJ" LED_3.5_CRGB 8563.21,2910.2 r180 top locked (schematic designator LD44)
KD106 "LTL760RGBEBJ" LED_3.5_CRGB 17276.68,3082.43 r270 top (schematic designator LD99)
KD107 "LTL760RGBEBJ" LED_3.5_CRGB 17276.48,1586.37 r270 top locked (schematic designator LD116)
KD108 "LTL760RGBEBJ" LED_3.5_CRGB 8208.9,2162.1 r180 top locked (schematic designator LD55)
KD109 "LTL760RGBEBJ" LED_3.5_CRGB 8917.56,1414.1 r180 top locked (schematic designator LD66)
KD110 "LTL760RGBEBJ" LED_3.5_CRGB 17480.59,4406.2 r180 top locked (schematic designator LD88)
LED1 "LTST-C19HE1WT-RZ" LED4P_SMD_1.6X1.6_CRGB 16107,5270 r90 top (schematic designator LD74)
LED2 "LTST-C19HE1WT-RZ" LED4P_SMD_1.6X1.6_CRGB 15597,5270 r90 top (schematic designator LD85)
LED3 "LTST-C19HE1WT-RZ" LED4P_SMD_1.6X1.6_CRGB 16637,5270 r90 top
LED4 "LTST-C19HE1WT-RZ" LED4P_SMD_1.6X1.6_CRGB 17177,5270 r90 top (schematic designator LD76)
LED5 "LTST-C19HE1WT-RZ" LED4P_SMD_1.6X1.6_CRGB 17687,5270 r90 top (schematic designator LD127)
LED6 "LTST-C19HE1WT-RZ" LED4P_SMD_1.6X1.6_CRGB 17687,4835 r90 top (schematic designator LD128)
LOGO1 "SW-PB-4P" SW-TACT-P4.5X6.5-Z6.2X6.2X5#1 17828,5147 r180 top locked
MUTE1 "SW-PB-4P" SW-TACT-P4.5X6.5-Z6.2X6.2X5#1 15724,5147 r180 top locked
Q1 "2301P" SOT-23 12832,2670 r0 bottom
Q2 "AO3400" SOT-23 11360,4740 r180 bottom
Q3 "AO3401" SOT-23 11080,4740 r180 bottom
Q4 "AO3400" SOT-23 11860,4740 r180 bottom
Q5 "AO3401" SOT-23 11580,4740 r180 bottom
Q6 "AO3400" SOT-23 12360,4740 r180 bottom
Q7 "AO3401" SOT-23 12080,4740 r180 bottom
Q8 "AO3400" SOT-23 12860,4740 r180 bottom
Q9 "AO3401" SOT-23 12580,4740 r180 bottom
Q10 "AO3400" SOT-23 13360,4740 r180 bottom
Q11 "AO3401" SOT-23 13080,4740 r180 bottom
Q12 "AO3400" SOT-23 13860,4740 r180 bottom
Q13 "AO3401" SOT-23 13580,4740 r180 bottom
Q14 "AO3400" SOT-23 14360,4740 r180 bottom
Q15 "AO3401" SOT-23 14080,4740 r180 bottom
Q16 "AO3400" SOT-23 16037,4640 r180 bottom
Q17 "AO3401" SOT-23 15757,4640 r180 bottom
Q18 "AO3400" SOT-23 16657,4640 r180 bottom
Q19 "AO3401" SOT-23 16377,4640 r180 bottom
Q20 "AO3400" SOT-23 17277,4640 r180 bottom
Q21 "AO3401" SOT-23 16997,4640 r180 bottom
Q22 "AO3400" SOT-23 10860,4740 r180 bottom
Q23 "AO3401" SOT-23 10580,4740 r180 bottom
R1 "3K" R-0603 15097,5340 r90 top
R2 "1K" R-0603 12557,2630 r0 bottom
R3 "10K" R-0603 12687,2630 r0 bottom
R4 "180" R-0603 15227,5150 r0 top
R5 "300" R-0603 15327,5180 r90 top
R6 "1K" R-0603 11250,4750 r270 bottom (schematic designator R69)
R7 "1K" R-0603 11190,4750 r270 bottom (schematic designator R70)
R8 "0" R-0603 11470,4750 r90 bottom
R9 "4.7K" R-0603 11110,4620 r180 bottom (schematic designator R71)
R10 "0" R-0603 10980,4620 r180 bottom (schematic designator R72)
R11 "1K" R-0603 11750,4750 r270 bottom (schematic designator R74)
R12 "1K" R-0603 11690,4750 r270 bottom (schematic designator R75)
R13 "0" R-0603 11970,4750 r90 bottom (schematic designator R78)
R14 "4.7K" R-0603 11610,4620 r180 bottom (schematic designator R76)
R15 "0" R-0603 11480,4620 r180 bottom (schematic designator R77)
R16 "1K" R-0603 12250,4750 r270 bottom (schematic designator R79)
R17 "1K" R-0603 12190,4750 r270 bottom (schematic designator R80)
R18 "0" R-0603 12470,4750 r90 bottom (schematic designator R83)
R19 "4.7K" R-0603 12110,4620 r180 bottom (schematic designator R81)
R20 "0" R-0603 11980,4620 r180 bottom (schematic designator R82)
R21 "1K" R-0603 12750,4750 r270 bottom (schematic designator R84)
R22 "1K" R-0603 12690,4750 r270 bottom (schematic designator R85)
R23 "0" R-0603 12970,4750 r90 bottom (schematic designator R88)
R24 "4.7K" R-0603 12690,4620 r180 bottom (schematic designator R86)
R25 "0" R-0603 12560,4620 r180 bottom (schematic designator R87)
R26 "1K" R-0603 13250,4750 r270 bottom (schematic designator R89)
R27 "1K" R-0603 13190,4750 r270 bottom (schematic designator R90)
R28 "0" R-0603 13470,4750 r90 bottom (schematic designator R93)
R29 "4.7K" R-0603 13180,4620 r180 bottom (schematic designator R91)
R30 "0" R-0603 13050,4620 r180 bottom (schematic designator R92)
R31 "1K" R-0603 13750,4750 r270 bottom (schematic designator R94)
R32 "1K" R-0603 13690,4750 r270 bottom (schematic designator R95)
R33 "0" R-0603 13970,4750 r90 bottom (schematic designator R98)
R34 "4.7K" R-0603 13676.6,4620 r180 bottom (schematic designator R96)
R35 "0" R-0603 13550,4620 r180 bottom (schematic designator R97)
R36 "1K" R-0603 14250,4750 r270 bottom (schematic designator R99)
R37 "1K" R-0603 14190,4750 r270 bottom (schematic designator R100)
R38 "0" R-0603 14470,4750 r90 bottom (schematic designator R103)
R39 "4.7K" R-0603 14050,4620 r0 bottom (schematic designator R101)
R40 "0" R-0603 14180,4620 r0 bottom (schematic designator R102)
R41 "1K" R-0603 15927,4640 r270 bottom
R42 "1K" R-0603 15867,4640 r270 bottom
R43 "0" R-0603 16147,4650 r90 bottom (schematic designator R111)
R44 "4.7K" R-0603 15647,4640 r270 bottom (schematic designator R109)
R45 "0" R-0603 15587,4640 r90 bottom (schematic designator R112)
R46 "1K" R-0603 16547,4650 r270 bottom (schematic designator R115)
R47 "1K" R-0603 16487,4650 r270 bottom (schematic designator R113)
R48 "0" R-0603 16767,4650 r90 bottom (schematic designator R116)
R49 "4.7K" R-0603 16267,4650 r270 bottom (schematic designator R114)
R50 "0" R-0603 16207,4650 r90 bottom (schematic designator R117)
R51 "1K" R-0603 17167,4650 r270 bottom (schematic designator R120)
R52 "1K" R-0603 17107,4650 r270 bottom (schematic designator R118)
R53 "0" R-0603 17387,4650 r90 bottom (schematic designator R121)
R54 "4.7K" R-0603 16827,4650 r270 bottom (schematic designator R119)
R55 "0" R-0603 16887,4650 r90 bottom (schematic designator R122)
R56 "1K" R-0603 10750,4750 r270 bottom (schematic designator R125)
R57 "1K" R-0603 10690,4750 r270 bottom (schematic designator R123)
R58 "0" R-0603 10970,4750 r90 bottom (schematic designator R126)
R59 "4.7K" R-0603 10470,4750 r270 bottom (schematic designator R124)
R60 "0" R-0603 10400,4750 r90 bottom (schematic designator R127)
R61 "4.7K" R-0603 14684.64,1356.75 r0 bottom (schematic designator R157)
R62 "4.7K" R-0603 14684.64,1278.01 r0 bottom (schematic designator R156)
R63 "4.7K" R-0603 14684.64,1159.9 r0 bottom (schematic designator R155)
R64 "1.2K" R-0603 14684.64,1061.48 r180 bottom (schematic designator R7)
R65 "0" R-0603 14656,783.89 r270 bottom (schematic designator R134)
R66 "51" R-0603 14726,783.89 r270 bottom (schematic designator R8)
R67 "51" R-0603 14810,1409.89 r270 bottom (schematic designator R9)
R68 "51" R-0603 14796,783.89 r270 bottom (schematic designator R10)
R69 "51" R-0603 14880,1409.89 r270 bottom (schematic designator R11)
R70 "51" R-0603 14866,783.89 r270 bottom (schematic designator R12)
R71 "51" R-0603 14950,1409.89 r270 bottom (schematic designator R13)
R72 "51" R-0603 14936,783.89 r270 bottom (schematic designator R14)
R73 "51" R-0603 15020,1409.89 r270 bottom (schematic designator R15)
R74 "51" R-0603 15006,783.89 r270 bottom (schematic designator R16)
R75 "51" R-0603 15090,1409.89 r270 bottom (schematic designator R17)
R76 "51" R-0603 15076,783.89 r270 bottom (schematic designator R18)
R77 "51" R-0603 15160,1409.89 r270 bottom (schematic designator R19)
R78 "51" R-0603 15146,783.89 r270 bottom (schematic designator R20)
R79 "51" R-0603 15230,1409.89 r270 bottom (schematic designator R21)
R80 "51" R-0603 15216,783.89 r270 bottom (schematic designator R22)
R81 "0" R-0603 7460,929.89 r180 bottom
R82 "4.7K" R-0603 7020,929.89 r180 bottom (schematic designator R24)
R83 "1.2K" R-0603 7460,869.89 r0 bottom (schematic designator R28)
R84 "0" R-0603 14732.87,3247.8 r270 top
R85 "0" R-0603 7460,989.89 r0 bottom (schematic designator R136)
R86 "0" R-0603 14782.87,3247.8 r270 top
R87 "51" R-0603 7460,1049.89 r0 bottom (schematic designator R30)
R88 "51" R-0603 6850,1049.89 r0 bottom (schematic designator R31)
R89 "51" R-0603 7460,1109.89 r0 bottom (schematic designator R32)
R90 "2K" R-0603 15887,5390 r180 top (schematic designator R27)
R91 "51" R-0603 6850,1109.89 r0 bottom (schematic designator R33)
R92 "51" R-0603 7460,1169.89 r0 bottom (schematic designator R34)
R93 "51" R-0603 6850,1169.89 r0 bottom (schematic designator R36)
R94 "51" R-0603 7460,1229.89 r0 bottom (schematic designator R37)
R95 "51" R-0603 6850,1229.89 r0 bottom (schematic designator R38)
R96 "51" R-0603 7460,1289.89 r0 bottom (schematic designator R39)
R97 "51" R-0603 6850,1289.89 r0 bottom (schematic designator R40)
R98 "51" R-0603 7460,1349.89 r0 bottom (schematic designator R41)
R99 "2K" R-0603 16037,5470 r180 top (schematic designator R29)
R100 "47K" R-0603 12483.22,2052.74 r90 bottom
R101 "47K" R-0603 12583.22,2052.74 r90 bottom
R102 "47K" R-0603 12557,2550 r180 bottom
R103 "51" R-0603 6850,1349.89 r0 bottom (schematic designator R43)
R104 "51" R-0603 7460,1409.89 r0 bottom (schematic designator R44)
R105 "51" R-0603 6850,1409.89 r0 bottom (schematic designator R45)
R106 "51" R-0603 7460,1469.89 r0 bottom (schematic designator R46)
R107 "2K" R-0603 16377,5470 r180 top (schematic designator R35)
R108 "2K" R-0603 16717,5470 r180 top (schematic designator R42)
R109 "4.7K" R-0603 12687,2362.74 r180 bottom
R110 "1.2K" R-0603 5533.15,925 r0 bottom (schematic designator R49)
R111 "0" R-0603 5530.58,991.39 r0 bottom (schematic designator R135)
R112 "51" R-0603 5530.58,1051.39 r0 bottom (schematic designator R52)
R113 "51" R-0603 4930,1049.89 r0 bottom (schematic designator R53)
R114 "51" R-0603 5530.58,1111.39 r0 bottom (schematic designator R54)
R115 "51" R-0603 4929,1110.31 r0 bottom (schematic designator R55)
R116 "51" R-0603 5530.58,1171.39 r0 bottom (schematic designator R56)
R117 "51" R-0603 4929,1170.31 r0 bottom (schematic designator R57)
R118 "51" R-0603 5530.58,1231.39 r0 bottom (schematic designator R58)
R119 "51" R-0603 4929,1230.31 r0 bottom (schematic designator R59)
R120 "51" R-0603 5530.58,1291.39 r0 bottom (schematic designator R60)
R121 "51" R-0603 4929,1290.31 r0 bottom (schematic designator R61)
R122 "51" R-0603 5530.58,1351.39 r0 bottom (schematic designator R62)
R123 "51" R-0603 4929,1350.31 r0 bottom (schematic designator R63)
R124 "51" R-0603 5530.58,1411.39 r0 bottom (schematic designator R64)
R125 "51" R-0603 4929,1410.31 r0 bottom (schematic designator R65)
R126 "51" R-0603 5530.58,1471.39 r0 bottom (schematic designator R66)
R127 "22" R-0603 11269.13,212.92 r90 top
R128 "22" R-0603 12282,606.47 r180 top
R129 "22" R-0603 12442,606.47 r0 top
R130 "0" R-0603 14586,783.89 r90 bottom
SW1 "SW_PB_SPST" SW2_KS4B#1 432.08,5226.89 r0 top locked (schematic designator Prof)
SW2 "SW_PB_SPST" SW2_KS4B#1 1258.39,5226.89 r0 top locked (schematic designator ESC)
SW3 "SW_PB_SPST" SW2_KS4B#1 2676.38,5226.89 r0 top locked (schematic designator F1)
SW4 "SW_PB_SPST" SW2_KS4B#1 3424.38,5226.89 r0 top locked (schematic designator F2)
SW5 "SW_PB_SPST" SW2_KS4B#1 4172.38,5226.89 r0 top locked (schematic designator F3)
SW6 "SW_PB_SPST" SW2_KS4B#1 4920.39,5226.89 r0 top locked (schematic designator F4)
SW7 "SW_PB_SPST" SW2_KS4B#1 6062.39,5226.89 r0 top locked (schematic designator F5)
SW8 "SW_PB_SPST" SW2_KS4B#1 6810.05,5226.89 r0 top locked (schematic designator F6)
SW9 "SW_PB_SPST" SW2_KS4B#1 7558.13,5226.89 r0 top locked (schematic designator F7)
SW10 "SW_PB_SPST" SW2_KS4B#1 8306.16,5226.89 r0 top locked (schematic designator F8)
SW11 "SW_PB_SPST" SW2_KS4B#1 9447.98,5226.89 r0 top locked (schematic designator F9)
SW12 "SW_PB_SPST" SW2_KS4B#1 432.08,4203.29 r0 top locked (schematic designator M1)
SW13 "SW_PB_SPST" SW2_KS4B#1 1258.98,4203.29 r0 top locked (schematic designator `~)
SW14 "SW_PB_SPST" SW2_KS4B#1 2006.86,4203.29 r0 top locked (schematic designator 1)
SW15 "SW_PB_SPST" SW2_KS4B#1 2754.97,4203.29 r0 top locked (schematic designator 2)
SW16 "SW_PB_SPST" SW2_KS4B#1 3502.96,4203.29 r0 top locked (schematic designator 3)
SW17 "SW_PB_SPST" SW2_KS4B#1 4250.99,4203.29 r0 top locked (schematic designator 4)
SW18 "SW_PB_SPST" SW2_KS4B#1 4998.99,4203.29 r0 top locked (schematic designator 5)
SW19 "SW_PB_SPST" SW2_KS4B#1 5747.02,4203.29 r0 top locked (schematic designator 6)
SW20 "SW_PB_SPST" SW2_KS4B#1 6495.06,4203.29 r0 top locked (schematic designator 7)
SW21 "SW_PB_SPST" SW2_KS4B#1 7243.13,4203.29 r0 top locked (schematic designator 8)
SW22 "SW_PB_SPST" SW2_KS4B#1 7991.12,4203.29 r0 top locked (schematic designator 9)
SW23 "SW_PB_SPST" SW2_KS4B#1 432.08,3454.89 r0 top locked (schematic designator M2)
SW24 "SW_PB_SPST" SW2_KS4B#1 1436.03,3454.89 r0 top locked (schematic designator TAB)
SW25 "SW_PB_SPST" SW2_KS4B#1 2361.42,3454.89 r0 top locked (schematic designator Q)
SW26 "SW_PB_SPST" SW2_KS4B#1 3109.3,3454.89 r0 top locked (schematic designator W)
SW27 "SW_PB_SPST" SW2_KS4B#1 3857.33,3454.89 r0 top locked (schematic designator E)
SW28 "SW_PB_SPST" SW2_KS4B#1 4605.32,3454.89 r0 top locked (schematic designator R)
SW29 "SW_PB_SPST" SW2_KS4B#1 5353.4,3454.89 r0 top locked (schematic designator T)
SW30 "SW_PB_SPST" SW2_KS4B#1 6101.39,3454.89 r0 top locked (schematic designator Y)
SW31 "SW_PB_SPST" SW2_KS4B#1 6849.46,3454.89 r0 top locked (schematic designator U)
SW32 "SW_PB_SPST" SW2_KS4B#1 7597.5,3454.89 r0 top locked (schematic designator I)
SW33 "SW_PB_SPST" SW2_KS4B#1 8345.53,3454.89 r0 top locked (schematic designator O)
SW34 "SW_PB_SPST" SW2_KS4B#1 432.08,2707.29 r0 top locked (schematic designator M3)
SW35 "SW_PB_SPST" SW2_KS4B#1 1544.3,2707.29 r0 top locked (schematic designator "Caps Lock")
SW36 "SW_PB_SPST" SW2_KS4B#1 2577.76,2707.29 r0 top locked (schematic designator A)
SW37 "SW_PB_SPST" SW2_KS4B#1 3325.83,2707.29 r0 top locked (schematic designator S)
SW38 "SW_PB_SPST" SW2_KS4B#1 4073.86,2707.29 r0 top locked (schematic designator D)
SW39 "SW_PB_SPST" SW2_KS4B#1 4821.91,2707.29 r0 top locked (schematic designator F)
SW40 "SW_PB_SPST" SW2_KS4B#1 5569.94,2707.29 r0 top locked (schematic designator G)
SW41 "SW_PB_SPST" SW2_KS4B#1 6317.97,2707.29 r0 top locked (schematic designator H)
SW42 "SW_PB_SPST" SW2_KS4B#1 7066,2707.29 r0 top locked (schematic designator J)
SW43 "SW_PB_SPST" SW2_KS4B#1 7814.03,2707.29 r0 top locked (schematic designator K)
SW44 "SW_PB_SPST" SW2_KS4B#1 8562.02,2707.29 r0 top locked (schematic designator L)
SW45 "SW_PB_SPST" SW2_KS4B#1 432.08,1959.19 r0 top locked (schematic designator M4)
SW46 "SW_PB_SPST" SW2_KS4B#1 1741.15,1959.19 r0 top locked (schematic designator L-SHIFT)
SW47 "SW_PB_SPST" SW2_KS4B#1 2971.47,1959.19 r0 top locked (schematic designator Z)
SW48 "SW_PB_SPST" SW2_KS4B#1 3719.53,1959.19 r0 top locked (schematic designator X)
SW49 "SW_PB_SPST" SW2_KS4B#1 4467.54,1959.19 r0 top locked (schematic designator C)
SW50 "SW_PB_SPST" SW2_KS4B#1 5215.58,1959.19 r0 top locked (schematic designator V)
SW51 "SW_PB_SPST" SW2_KS4B#1 5963.61,1959.19 r0 top locked (schematic designator B)
SW52 "SW_PB_SPST" SW2_KS4B#1 6711.64,1959.19 r0 top locked (schematic designator N)
SW53 "SW_PB_SPST" SW2_KS4B#1 7459.67,1959.19 r0 top locked (schematic designator M)
SW54 "SW_PB_SPST" SW2_KS4B#1 8207.71,1959.19 r0 top locked (schematic designator ,<)
SW55 "SW_PB_SPST" SW2_KS4B#1 432.08,1211.19 r0 top locked (schematic designator M5)
SW56 "SW_PB_SPST" SW2_KS4B#1 1436.04,1211.19 r0 top (schematic designator L-Ctrl)
SW57 "SW_PB_SPST" SW2_KS4B#1 2361.24,1211.19 r0 top locked (schematic designator L-WIN)
SW58 "SW_PB_SPST" SW2_KS4B#1 3286.44,1211.19 r0 top locked (schematic designator L-ALT)
SW59 "SW_PB_SPST" SW2_KS4B#2 6101.41,1211.19 r0 top locked (schematic designator Space1)
SW60 "SW_PB_SPST" SW2_KS4B#1 8916.38,1211.19 r0 top locked (schematic designator R-ALT)
SW61 "SW_PB_SPST" SW2_KS4B#1 10195.89,5226.89 r0 top locked (schematic designator F10)
SW62 "SW_PB_SPST" SW2_KS4B#1 10944.08,5226.89 r0 top locked (schematic designator F11)
SW63 "SW_PB_SPST" SW2_KS4B#1 11692,5226.89 r0 top locked (schematic designator F12)
SW64 "SW_PB_SPST" SW2_KS4B#1 12715.58,5226.89 r0 top locked (schematic designator "Print Scrn")
SW65 "SW_PB_SPST" SW2_KS4B#1 13463.65,5226.89 r0 top locked (schematic designator "Scroll Lock")
SW66 "SW_PB_SPST" SW2_KS4B#1 14211.65,5226.89 r0 top locked (schematic designator "Pause Break")
SW67 "SW_PB_SPST" SW2_KS4B#1 8739.2,4203.29 r0 top locked (schematic designator 0))
SW68 "SW_PB_SPST" SW2_KS4B#1 9487.27,4203.29 r0 top locked (schematic designator -_)
SW69 "SW_PB_SPST" SW2_KS4B#1 10235.26,4203.29 r0 top locked (schematic designator +=)
SW70 "SW_PB_SPST" SW2_KS4B#1 11337.7,4203.29 r0 top locked (schematic designator BackSpace)
SW71 "SW_PB_SPST" SW2_KS4B#1 12715.58,4203.29 r0 top locked (schematic designator INS)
